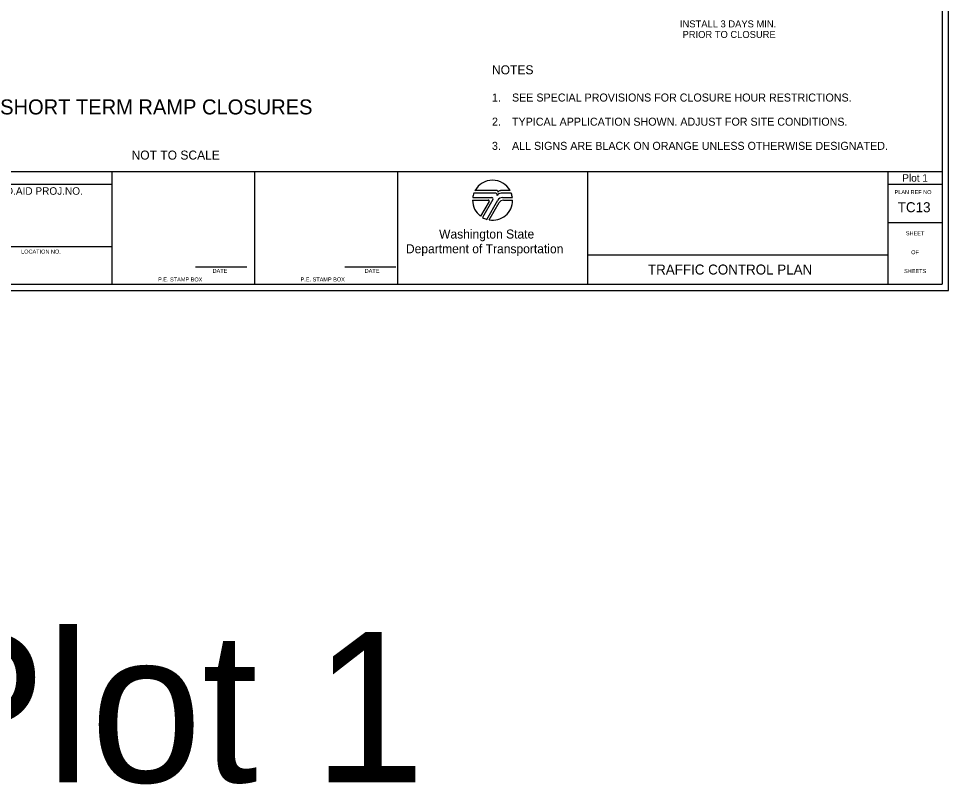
# Model space of a CAD drawing. Extents: x 99988 to 100172, y 99995 to 100047.
# Drawn here: x 100006.52 to 100015.81, y 99995.01 to 100002.65 of the extents above; entities that cross this region are included whole.
import ezdxf

# ---------------------------------------------------------------- set-up
doc = ezdxf.new("R2010")
doc.units = 0
for name, color, linetype in [('Level 20', 7, 'Continuous'), ('SH_DE_DetailBody1Text', 7, 'Continuous'), ('SH_DE_DetailHeading1Text', 7, 'Continuous'), ('SH_DE_DetailHeading3Text', 7, 'Continuous'), ('SH_GI_PlotLimits', 7, 'Continuous'), ('SH_GI_SheetBorder', 7, 'Continuous'), ('SH_GI_SheetLocationText', 7, 'Continuous'), ('SH_GI_SheetTextInCells', 7, 'Continuous'), ('SH_GI_TitleBlockText', 7, 'Continuous'), ('SH_GI_WSDOTLogo', 7, 'Continuous')]:
    doc.layers.add(name, color=color, linetype=linetype)

msp = doc.modelspace()

# ---------------------------------------------------------------- linework, layer by layer
at = {"layer": 'SH_GI_PlotLimits'}
msp.add_lwpolyline([(99999.3125, 99999.9375), (100015.8125, 99999.9375), (100015.8125, 100010.4375), (99999.3125, 100010.4375)], close=True, dxfattribs=at)
at = {"layer": 'SH_GI_SheetBorder'}
for p, q in [((100015.75, 100010.375), (100015.75, 100000)), ((100000, 100001.1259), (100015.75, 100001.1259)), ((100007.4566, 100000), (100007.4566, 100001.1259)), ((100008.8828, 100000), (100008.8828, 100001.1259)), ((100010.3089, 100001.1259), (100010.3089, 100000)), ((100012.2055, 100001.1259), (100012.2055, 100000)), ((100015.2079, 100001.1259), (100015.2079, 100000)), ((100000, 100001.0008), (100007.4566, 100001.0008)), ((100015.2079, 100001.0008), (100015.75, 100001.0008)), ((100015.2079, 100000.6176), (100015.75, 100000.6176)), ((100007.4566, 100000.3753), (100005.4466, 100000.3753)), ((100012.2055, 100000.2955), (100015.2079, 100000.2955)), ((100008.2903, 100000.1733), (100008.802, 100000.1733)), ((100009.7797, 100000.1733), (100010.2914, 100000.1733)), ((100000, 100000), (100015.75, 100000))]:
    msp.add_line(p, q, dxfattribs=at)
at = {"layer": 'SH_GI_WSDOTLogo'}
for p, q in [((100011.2894, 100000.9094), (100011.0697, 100000.9094)), ((100011.303, 100000.9354), (100011.0815, 100000.9354)), ((100011.433, 100000.9354), (100011.3351, 100000.9354)), ((100011.343, 100000.9094), (100011.3429, 100000.9094)), ((100011.4448, 100000.9094), (100011.343, 100000.9094)), ((100011.0572, 100000.84), (100011.2148, 100000.84)), ((100011.059, 100000.8661), (100011.2496, 100000.8661)), ((100011.222, 100000.8277), (100011.1364, 100000.6807)), ((100011.261, 100000.8464), (100011.1567, 100000.6672)), ((100011.1989, 100000.6487), (100011.3089, 100000.839)), ((100011.2244, 100000.6428), (100011.3242, 100000.8156)), ((100011.3558, 100000.8661), (100011.4555, 100000.8661)), ((100011.3655, 100000.8394), (100011.4572, 100000.8394))]:
    msp.add_line(p, q, dxfattribs=at)
for centre, radius, start, end in [((100011.2572, 100000.84), 0.2, 28.47865, 151.53204), ((100011.2572, 100000.84), 0.2, 159.69598, 172.50569), ((100011.2894, 100000.8946), 0.0148, 327.8418, 89.99855), ((100011.3429, 100000.861), 0.0484, 89.99529, 147.82376), ((100011.303, 100000.9263), 0.00903, 329.87418, 90.00328), ((100011.3352, 100000.9066), 0.0287, 90.00721, 148.16763), ((100011.2572, 100000.84), 0.2, 7.49431, 20.29406), ((100011.2572, 100000.84), 0.2, 179.99864, 232.84327), ((100011.2149, 100000.8318), 0.0082, 329.74356, 90), ((100011.2572, 100000.84), 0.2, 260.54554, 359.80857), ((100011.2497, 100000.853), 0.0131, 329.76834, 90), ((100011.3558, 100000.8119), 0.0542, 90, 149.99738), ((100011.3654, 100000.7918), 0.0476, 90, 150.05432), ((100011.2572, 100000.84), 0.2, 239.79292, 253.0448)]:
    msp.add_arc(centre, radius, start, end, dxfattribs=at)

# ---------------------------------------------------------------- texts
at = {"layer": 'Level 20'}
for s, height, p in [('NOTES', 0.09, (100011.2515, 100002.0975)), ('1.', 0.08, (100011.2515, 100001.8255)), ('SEE SPECIAL PROVISIONS FOR CLOSURE HOUR RESTRICTIONS.', 0.08, (100011.4515, 100001.8255)), ('2.', 0.08, (100011.2515, 100001.5843)), ('TYPICAL APPLICATION SHOWN. ADJUST FOR SITE CONDITIONS.', 0.08, (100011.4515, 100001.5843)), ('3.', 0.08, (100011.2515, 100001.343)), ('ALL SIGNS ARE BLACK ON ORANGE UNLESS OTHERWISE DESIGNATED.', 0.08, (100011.4515, 100001.343))]:
    msp.add_text(s, height=height, dxfattribs=at).set_placement(p)
at = {"layer": 'SH_DE_DetailBody1Text'}
for s, p in [('INSTALL 3 DAYS MIN.', (100013.1298, 100002.566)), ('PRIOR TO CLOSURE', (100013.1556, 100002.4605))]:
    msp.add_text(s, height=0.07, dxfattribs=at).set_placement(p)
at = {"layer": 'SH_DE_DetailHeading1Text'}
msp.add_text(' SHORT TERM RAMP CLOSURES', height=0.15, dxfattribs=at).set_placement((100006.2813, 100001.6968))
at = {"layer": 'SH_DE_DetailHeading3Text'}
msp.add_text('NOT TO SCALE', height=0.09, dxfattribs=at).set_placement((100007.6497, 100001.2457))
at = {"layer": 'SH_GI_SheetBorder'}
msp.add_text('PLAN REF NO', height=0.040032, dxfattribs=at).set_placement((100015.2747, 100000.9008))
at = {"layer": 'SH_GI_SheetLocationText'}
for height, p in [(0.075, (100015.3518, 100001.025)), (1.5, (100005.4547, 99995.0267))]:
    msp.add_text('Plot 1', height=height, dxfattribs=at).set_placement(p)
at = {"layer": 'SH_GI_SheetTextInCells'}
for s, height, p in [('FED.AID PROJ.NO.', 0.07506, (100006.2652, 100000.8945)), ('Washington State', 0.090072, (100010.7229, 100000.4571)), ('SHEET', 0.04003, (100015.3877, 100000.4896)), ('Department of Transportation', 0.090072, (100010.3916, 100000.3101)), ('LOCATION NO.', 0.040032, (100006.5465, 100000.3067)), ('OF', 0.04003, (100015.4406, 100000.3008)), ('DATE', 0.04003, (100008.4597, 100000.1141)), ('DATE', 0.04003, (100009.9794, 100000.1141)), ('SHEETS', 0.04003, (100015.3698, 100000.112)), ('P.E. STAMP BOX', 0.040032, (100007.915, 100000.0286)), ('P.E. STAMP BOX', 0.040032, (100009.339, 100000.0286))]:
    msp.add_text(s, height=height, dxfattribs=at).set_placement(p)
at = {"layer": 'SH_GI_TitleBlockText'}
for s, p in [('TC13', (100015.3067, 100000.72)), ('TRAFFIC CONTROL PLAN', (100012.8099, 100000.0977))]:
    msp.add_text(s, height=0.1, dxfattribs=at).set_placement(p)

doc.saveas('drawing.dxf')
